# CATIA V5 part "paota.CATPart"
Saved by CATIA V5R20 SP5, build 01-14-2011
Part number: paota
Bounding box of the stored display mesh (mm): x -1244.203 to 1598.859, y -1153.558 to 1153.558, z 0 to 1110
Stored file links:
  C:\Documents and Settings\Student\桌面\zuoping\paota.CATPart
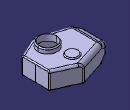
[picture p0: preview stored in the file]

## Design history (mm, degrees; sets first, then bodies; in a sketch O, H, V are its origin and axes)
Body1 (main body)
  Sketch1 on xy-plane, origin (0, 0, 0), H (1, 0, 0), V (0, 1, 0)
    circle A1 centre (0, 0) radius 790
    circle A2 centre (0, 0) radius 820
    radius A1 = 790
    radius A2 = 820
  Pad1: profile Sketch1, direction (0, 0, 1), length 60
  Plane1: type Offset, RefPlane xy-plane, Offset 60
  Sketch2 on Plane1, origin (0, 0, 60), H (1, 0, 0), V (0, 1, 0)
    axis line L1 (-2947.561, 0) -> (3037.3967, 0)
    point P1 (-2947.561, 0)
    point P2 (3037.3967, 0)
    point P3 (-1200, 0)
    line L2 (-1200, 0) -> (-1200, 634.9877)
    line L3 (-1200, 634.9877) -> (468.8589, 1160.5879)
    point P5 (468.8589, 1160.5879)
    line L4 (468.8589, 1160.5879) -> (1598.8589, 650)
    point P6 (1598.8589, 650)
    line L5 (1598.8589, 650) -> (1598.8589, 0)
    point P7 (1598.8589, 0)
    line L6 (1598.8589, 0) -> (1598.8589, -650)
    point P8 (1598.8589, -650)
    line L7 (1598.8589, -650) -> (468.8589, -1160.5879)
    point P9 (468.8589, -1160.5879)
    line L8 (468.8589, -1160.5879) -> (-1200, -634.9877)
    point P10 (-1200, -634.9877)
    line L9 (-1200, -634.9877) -> (-1200, 0)
    point P11 (-1200, 0)
    length L5 = 650
    length L6 = 650
    distance P5 L5 = 1130
    distance P9 L6 = 1130
    distance P5 P6 = 1240
    distance P8 P9 = 1240
    length L3 = 1749.6702
    length L8 = 1749.6702
    distance O L2 = 1200
    coincidence: P1 H, P3 L1, L4 P2, P7 L1, P10 L2, P11 P3
    horizontal: L1 H
    vertical: L2 V, L5 V, L6 V, L9 V
  Pad2: profile Sketch2, direction (0, 0, 1), length 830
  Sketch3 on zx-plane, origin (0, 0, 0), H (-1, 0, 0), V (0, 0, 1)
    line L1 (1460.1769, 515.3556) -> (659.1096, 948.5076)
    line L2 (659.1096, 948.5076) -> (1460.1769, 948.5076)
    line L3 (1460.1769, 948.5076) -> (1460.1769, 515.3556)
    horizontal: L2 H
    vertical: L3 V
  Pocket1: profile Sketch3, direction (0, -1, 0), length 830, mirrored extent
  Sketch4 on zx-plane, origin (0, 0, 0), H (-1, 0, 0), V (0, 0, 1)
    line L1 (659.0989, -87.005) -> (1263.2932, 305.5387)
    line L2 (1263.2932, 305.5387) -> (1860.699, 305.5387)
    line L3 (1860.699, 305.5387) -> (1860.699, -87.005)
    line L4 (1860.699, -87.005) -> (659.0989, -87.005)
    horizontal: L2 H, L4 H
    vertical: L3 V
  Pocket2: profile Sketch4, direction (0, -1, 0), length 830, mirrored extent
  Fillet1: radius 300, on edge [face of Pad2 from Sketch2.L8 | face of Pad2 from Sketch2.L9]; edge [face of Pad2 from Sketch2.L2 | face of Pad2 from Sketch2.L3]
  Fillet2: radius 200, on edge [face of Pocket1 from Sketch3.L1 | face of Pad2 from Sketch2.L9]; edge [face of Pad2 from Sketch2.L9 | face of Pocket2 from Sketch4.L1]
  Fillet3: radius 200, on edge [end face of Pad2 | face of Pocket1 from Sketch3.L1]
  Fillet4: radius 100, on edge [face of Pad2 from Sketch2.L7 | end face of Pad2]
  Fillet5: radius 100, on edge [face of Pad2 from Sketch2.L4 | end face of Pad2]
  Fillet6: radius 50, on edge [face of Pad2 from Sketch2.L5 | end face of Pad2]
  Fillet7: radius 50, on edge [start face of Pad2 | face of Pad2 from Sketch2.L5]
  Sketch5 on face of Pad2 from Sketch2.L9, origin (-1200, 0, 0), H (0, -1, 0), V (0, 0, 1)
    point P1 (0, 447.4066)
    line L1 (327.0084, 636.001) -> (327.0084, 258.8122)
    line L2 (327.0084, 258.8122) -> (-327.0084, 258.8122)
    line L3 (-327.0084, 258.8122) -> (-327.0084, 636.001)
    line L4 (-327.0084, 636.001) -> (327.0084, 636.001)
    coincidence: P1 V
    vertical: L1 V, L3 V
    horizontal: L2 H, L4 H
    equidistance: L1 L3 P1, L2 L4 P1
  Pocket3: profile Sketch5, direction (1, 0, 0), length 830
  Sketch6 on end face of Pad2, origin (0, 0, 890), H (1, 0, 0), V (0, 1, 0)
    circle A1 centre (613.4511, -408.78) radius 457.6228
  Pad3: profile Sketch6, direction (0, 0, 1), length 220
  Fillet8: radius 50, on edge [face of Pad3 from Sketch6.A1 | end face of Pad3]
  Sketch7 on end face of Pad2, origin (0, 0, 890), H (1, 0, 0), V (0, 1, 0)
    circle A1 centre (367.1685, 509.2045) radius 298.9924
  Pad4: profile Sketch7, direction (0, 0, 1), length 50
  Fillet9: radius 40, on edge [face of Pad4 from Sketch7.A1 | end face of Pad4]
  Sketch8 on end face of Pad3, origin (0, 0, 1110), H (1, 0, 0), V (0, 1, 0)
    circle A1 centre (606.3812, -403.2704) radius 403.2704
  Pocket4: profile Sketch8, direction (0, 0, -1), length 300
  Sketch9 on face of Pad2 from Sketch2.L2, origin (-1200, 0, 0), H (0, -1, 0), V (0, 0, 1)
    line L1 (-324.5953, 537.6561) -> (325.4047, 537.6561)
    line L2 (325.4047, 537.6561) -> (325.4047, 382.5954)
    line L3 (325.4047, 382.5954) -> (-324.5953, 382.5954)
    line L4 (-324.5953, 382.5954) -> (-324.5953, 537.6561)
    line L5 (-274.5953, 527.6561) -> (275.4047, 527.6561)
    line L6 (275.4047, 527.6561) -> (275.4047, 392.5954)
    line L7 (275.4047, 392.5954) -> (-274.5953, 392.5954)
    line L8 (-274.5953, 392.5954) -> (-274.5953, 527.6561)
    distance L6 L2 = 50
    distance L8 L4 = 50
    distance L5 L1 = 10
    distance L7 L3 = 10
    distance L8 L6 = 550
    horizontal: L1 H, L3 H, L5 H, L7 H
    vertical: L2 V, L4 V, L6 V, L8 V
  Pad5: profile Sketch9, direction (1, 0, 0), length 300
  Sketch10 on face of Pad5 from Sketch9.L8, origin (0, 274.5953, 0), H (1, 0, 0), V (0, 0, 1)
    circle A1 centre (-1204.3979, 466.1967) radius 40
    radius A1 = 40
  Pocket5: profile Sketch10, direction (0, 1, 0), length 40
  Mirror1: of Pocket5, about zx-plane
  Shell1: ExtOffset 0, Face end face of Pocket4, IntOffset 1
  Shell2: ExtOffset 0, Face face of Shell1, IntOffset 1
